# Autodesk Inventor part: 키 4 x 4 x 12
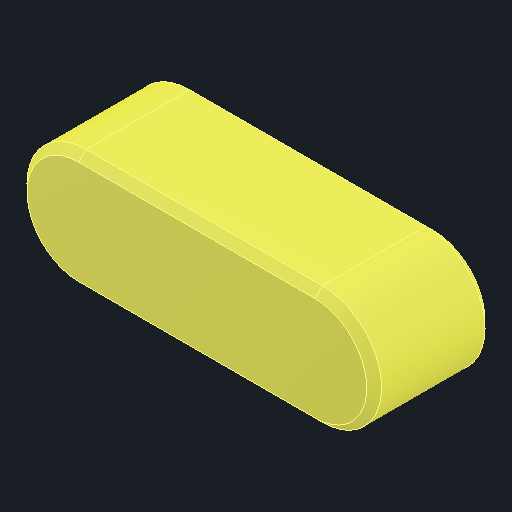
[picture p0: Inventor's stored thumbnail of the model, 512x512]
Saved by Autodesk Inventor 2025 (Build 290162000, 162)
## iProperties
Created: 2025-08
Part Number: 키 4 x 4 x 12
Material: 강철, 연강
Description: 키 및 해당 키홈
Document SubType Name: Modeling
Designer: infra15
Density: 7.85 g/cm^3
Appearance: 기본값
Author: jhkim
Sending System: Autodesk Inventor 2026
Preprocessor: ST-DEVELOPER v20.1
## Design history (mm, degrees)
feature "Solid1"
node "솔리드1"
